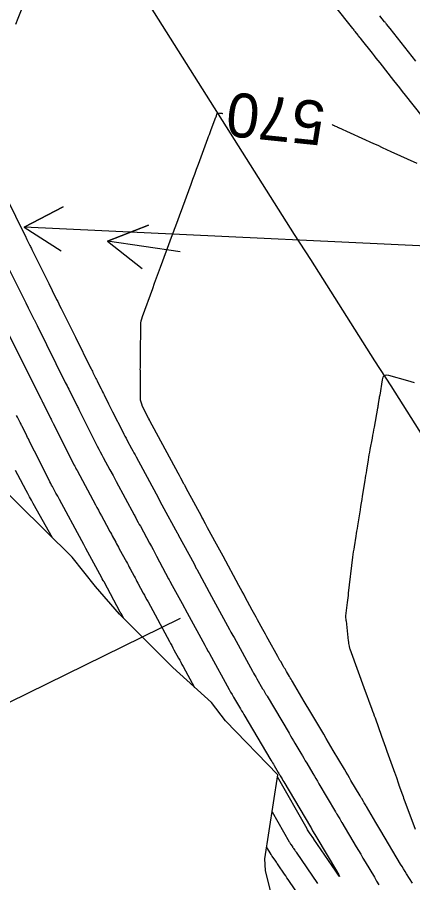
# Model space of a CAD drawing. Extents: x 954385 to 988206, y 1868364 to 1924553.
# Drawn here: x 957284.9 to 957338.9, y 1920532.9 to 1920650.9 of the extents above; entities that cross this region are included whole.
import ezdxf

# ---------------------------------------------------------------- set-up
doc = ezdxf.new("R2010")
doc.units = 0
for name, color, linetype in [('24', 7, 'Continuous'), ('26', 7, 'Continuous'), ('5', 7, 'Continuous'), ('6', 7, 'Continuous'), ('7', 7, 'Continuous'), ('Default', 7, 'Continuous')]:
    doc.layers.add(name, color=color, linetype=linetype)

msp = doc.modelspace()

# ---------------------------------------------------------------- linework, layer by layer
at = {"layer": '24'}
msp.add_lwpolyline([(957321.31, 1920524.25), (957318.76, 1920534.56), (957318.67, 1920536.13), (957320.46, 1920547.59), (957313.34, 1920554.95), (957311.39, 1920557.45), (957306.13, 1920562.25), (957298.87, 1920569.52), (957295.57, 1920573.3), (957292.4, 1920577.31), (957285.05, 1920584.53), (957280.11, 1920589.4)], dxfattribs=at)
at = {"layer": '26'}
for points in [[(957357.13, 1920618.93), (957285.84, 1920622.32), (957291.17, 1920625.07), (957285.84, 1920622.32), (957290.89, 1920619.08)], [(957307.13, 1920618.93), (957297.23, 1920620.38), (957302.81, 1920622.59), (957297.23, 1920620.38), (957301.94, 1920616.66)], [(957307.13, 1920568.93), (957203.18, 1920517.93), (957206.53, 1920522.91), (957203.18, 1920517.93), (957209.17, 1920517.53)]]:
    msp.add_lwpolyline(points, dxfattribs=at)
at = {"layer": '6'}
for points in [[(957338.83, 1920532.81), (957338.02, 1920534.11), (957337.82, 1920534.44), (957337.62, 1920534.77), (957337.42, 1920535.1), (957337.22, 1920535.43), (957334.53, 1920539.96), (957333.84, 1920541.1), (957332.55, 1920543.28), (957332.52, 1920543.34), (957332.48, 1920543.39), (957332.45, 1920543.45), (957332.42, 1920543.5), (957332.25, 1920543.78), (957332.19, 1920543.9), (957332.15, 1920543.95), (957331.9, 1920544.39), (957331.84, 1920544.48), (957331.79, 1920544.57), (957331.74, 1920544.66), (957331.68, 1920544.76), (957330.44, 1920546.85), (957330.22, 1920547.22), (957330, 1920547.6), (957329.77, 1920547.98), (957329.55, 1920548.36), (957328.03, 1920550.92), (957327.7, 1920551.48), (957327.37, 1920552.03), (957327.04, 1920552.58), (957326.72, 1920553.14), (957324.96, 1920556.11), (957324.06, 1920557.62), (957322.46, 1920560.32), (957322.36, 1920560.49), (957322.26, 1920560.66), (957322.15, 1920560.84), (957322.05, 1920561.01), (957321.64, 1920561.71), (957321.54, 1920561.88), (957321.44, 1920562.05), (957321.34, 1920562.21), (957321.25, 1920562.38), (957320.85, 1920563.05), (957320.75, 1920563.22), (957320.66, 1920563.39), (957320.56, 1920563.56), (957320.47, 1920563.73), (957319.16, 1920566.1), (957318.97, 1920566.43), (957318.79, 1920566.77), (957318.61, 1920567.1), (957318.43, 1920567.43), (957317.69, 1920568.75), (957317.51, 1920569.09), (957317.33, 1920569.42), (957317.15, 1920569.75), (957316.97, 1920570.08), (957316.02, 1920571.83), (957315.8, 1920572.23), (957315.58, 1920572.63), (957315.37, 1920573.03), (957315.15, 1920573.43), (957312.98, 1920577.42), (957312.76, 1920577.84), (957312.53, 1920578.25), (957312.31, 1920578.67), (957312.08, 1920579.08), (957310.88, 1920581.31), (957310.74, 1920581.57), (957310.6, 1920581.83), (957310.32, 1920582.36), (957310.25, 1920582.49), (957310.18, 1920582.62), (957310.1, 1920582.75), (957310.03, 1920582.88), (957308.23, 1920586.21), (957307.86, 1920586.9), (957307.8, 1920587), (957307.75, 1920587.1), (957307.69, 1920587.19), (957307.64, 1920587.29), (957307.22, 1920588.08), (957307.04, 1920588.41), (957306.86, 1920588.73), (957303, 1920595.88), (957302.98, 1920595.91), (957302.97, 1920595.94), (957302.95, 1920595.97), (957302.94, 1920596), (957302.81, 1920596.25), (957302, 1920597.85), (957301.88, 1920598.14), (957301.79, 1920598.43), (957301.74, 1920598.72), (957301.72, 1920599.03), (957301.71, 1920600.69), (957301.71, 1920600.93), (957301.71, 1920601.17), (957301.7, 1920601.42), (957301.7, 1920601.66), (957301.7, 1920602.69), (957301.69, 1920602.91), (957301.7, 1920603.12), (957301.7, 1920603.33), (957301.7, 1920603.54), (957301.72, 1920604.8), (957301.72, 1920605.22), (957301.74, 1920606.48), (957301.74, 1920606.76), (957301.75, 1920607.04), (957301.75, 1920607.32), (957301.75, 1920607.6), (957301.77, 1920608.9), (957301.78, 1920609.2), (957301.83, 1920609.51), (957301.89, 1920609.8), (957301.99, 1920610.1), (957303.38, 1920613.92), (957303.65, 1920614.65), (957303.92, 1920615.39), (957304.19, 1920616.12), (957304.46, 1920616.86), (957306.08, 1920621.28), (957306.17, 1920621.52), (957306.26, 1920621.77), (957306.35, 1920622.01), (957306.44, 1920622.25), (957306.8, 1920623.23), (957306.89, 1920623.47), (957306.98, 1920623.72), (957307.07, 1920623.96), (957307.16, 1920624.2), (957308.62, 1920628.18), (957308.87, 1920628.86), (957309.12, 1920629.53), (957309.37, 1920630.21), (957309.62, 1920630.88), (957310.92, 1920634.39), (957311.02, 1920634.66), (957311.12, 1920634.93), (957311.22, 1920635.2), (957311.32, 1920635.47), (957311.91, 1920637.07), (957311.96, 1920637.22), (957311.98, 1920637.26), (957312.07, 1920637.49), (957312.09, 1920637.57), (957312.12, 1920637.65), (957312.18, 1920637.8), (957312.2, 1920637.84), (957312.22, 1920637.86), (957312.25, 1920637.87), (957312.29, 1920637.87), (957312.5, 1920637.86), (957312.58, 1920637.85), (957312.81, 1920637.83), (957312.9, 1920637.82), (957312.96, 1920637.81)], [(957327.88, 1920636.28), (957327.91, 1920636.26), (957327.99, 1920636.23), (957328.06, 1920636.2), (957328.13, 1920636.17), (957328.2, 1920636.13), (957328.48, 1920636.01), (957328.55, 1920635.98), (957328.62, 1920635.94), (957328.69, 1920635.91), (957328.76, 1920635.88), (957333.5, 1920633.73), (957334.09, 1920633.46), (957334.69, 1920633.18), (957335.29, 1920632.91), (957335.89, 1920632.64), (957339.42, 1920631.03)], [(957289.71, 1920579.95), (957287.08, 1920584.62), (957286.83, 1920585.06), (957286.58, 1920585.51), (957286.34, 1920585.96), (957286.1, 1920586.4), (957284.97, 1920588.5), (957284.65, 1920589.1)], [(957325.31, 1920528.3), (957322.05, 1920533.08), (957321.88, 1920533.33), (957321.71, 1920533.58), (957321.54, 1920533.83), (957321.37, 1920534.08), (957320.51, 1920535.33), (957320.42, 1920535.46), (957320.34, 1920535.58), (957320.26, 1920535.7), (957320.17, 1920535.82), (957319.7, 1920536.5), (957319.66, 1920536.56), (957319.59, 1920536.66), (957319.58, 1920536.68), (957319.56, 1920536.7), (957319.55, 1920536.73), (957319.54, 1920536.75), (957318.93, 1920537.81)]]:
    msp.add_lwpolyline(points, dxfattribs=at)
at = {"layer": '7'}
for points in [[(957287.37, 1920656.87), (957284.99, 1920650.74), (957284.67, 1920649.94)], [(957340.17, 1920637.42), (957337.88, 1920640.3), (957337.49, 1920640.81), (957337.09, 1920641.31), (957336.69, 1920641.82), (957336.29, 1920642.32), (957334.42, 1920644.69), (957334.15, 1920645.02), (957333.89, 1920645.35), (957333.63, 1920645.68), (957333.36, 1920646.02), (957331.86, 1920647.91), (957331.79, 1920648.01), (957331.71, 1920648.11), (957331.48, 1920648.39), (957331.41, 1920648.49), (957331.02, 1920648.99), (957330.94, 1920649.08), (957330.86, 1920649.18), (957330.78, 1920649.28), (957330.7, 1920649.38), (957325.88, 1920655.5)], [(957339.28, 1920644.95), (957335.78, 1920649.37), (957335.3, 1920649.98), (957335.23, 1920650.06), (957335.17, 1920650.15), (957335.1, 1920650.24), (957335.03, 1920650.32), (957334.4, 1920651.12)], [(957281.76, 1920629.62), (957286.07, 1920620.93), (957286.12, 1920620.83), (957286.22, 1920620.63), (957286.27, 1920620.53), (957286.63, 1920619.78), (957286.7, 1920619.65), (957286.77, 1920619.52), (957286.83, 1920619.38), (957286.9, 1920619.25), (957289.2, 1920614.6), (957289.66, 1920613.68), (957290.27, 1920612.45), (957290.43, 1920612.14), (957290.58, 1920611.83), (957290.73, 1920611.52), (957290.89, 1920611.21), (957292.84, 1920607.3), (957294.91, 1920603.12), (957294.99, 1920602.96), (957295.07, 1920602.8), (957295.15, 1920602.64), (957295.23, 1920602.48), (957295.55, 1920601.84), (957295.63, 1920601.68), (957295.71, 1920601.52), (957295.79, 1920601.36), (957295.87, 1920601.2), (957296.34, 1920600.26), (957296.44, 1920600.05), (957296.55, 1920599.84), (957296.65, 1920599.63), (957296.76, 1920599.42), (957297.37, 1920598.21), (957297.5, 1920597.94), (957297.64, 1920597.67), (957297.78, 1920597.4), (957297.91, 1920597.12), (957299.3, 1920594.37), (957299.45, 1920594.08), (957299.6, 1920593.79), (957299.75, 1920593.51), (957299.9, 1920593.22), (957300.51, 1920592.09), (957300.67, 1920591.81), (957300.82, 1920591.52), (957300.97, 1920591.24), (957301.13, 1920590.96), (957303.84, 1920585.94), (957304.11, 1920585.44), (957304.38, 1920584.95), (957304.64, 1920584.45), (957304.91, 1920583.95), (957306.49, 1920581.04), (957306.73, 1920580.6), (957306.77, 1920580.53), (957306.8, 1920580.47), (957306.84, 1920580.41), (957306.87, 1920580.34), (957309.02, 1920576.37), (957309.13, 1920576.15), (957309.16, 1920576.1), (957309.19, 1920576.04), (957309.38, 1920575.69), (957309.41, 1920575.64), (957311.42, 1920571.93), (957313.86, 1920567.45), (957313.91, 1920567.35), (957313.96, 1920567.26), (957314.01, 1920567.17), (957314.06, 1920567.07), (957314.32, 1920566.61), (957314.48, 1920566.33), (957317, 1920561.75), (957317.14, 1920561.49), (957317.29, 1920561.23), (957317.44, 1920560.97), (957317.59, 1920560.72), (957318.39, 1920559.34), (957318.49, 1920559.18), (957318.59, 1920559.01), (957318.79, 1920558.67), (957318.84, 1920558.59), (957318.89, 1920558.5), (957318.94, 1920558.42), (957318.99, 1920558.34), (957321.99, 1920553.27), (957322.19, 1920552.93), (957322.39, 1920552.59), (957322.6, 1920552.25), (957322.8, 1920551.91), (957323.6, 1920550.55), (957323.81, 1920550.21), (957324.01, 1920549.87), (957324.21, 1920549.53), (957324.41, 1920549.19), (957325.24, 1920547.78), (957325.45, 1920547.43), (957325.66, 1920547.09), (957325.86, 1920546.74), (957326.07, 1920546.39), (957328.33, 1920542.58), (957328.38, 1920542.49), (957328.43, 1920542.41), (957328.48, 1920542.32), (957328.52, 1920542.24), (957328.75, 1920541.86), (957328.82, 1920541.74), (957328.9, 1920541.61), (957329.04, 1920541.35), (957329.08, 1920541.29), (957329.12, 1920541.23), (957329.16, 1920541.16), (957329.19, 1920541.1), (957331.15, 1920537.81), (957331.46, 1920537.29), (957331.77, 1920536.77), (957332.08, 1920536.25), (957332.39, 1920535.73), (957333.63, 1920533.64), (957333.94, 1920533.12), (957334.26, 1920532.6)], [(957283.86, 1920616.43), (957286.07, 1920611.97), (957286.41, 1920611.29), (957287.12, 1920609.85), (957287.16, 1920609.77), (957287.2, 1920609.69), (957287.24, 1920609.61), (957287.28, 1920609.52), (957287.61, 1920608.88), (957291.46, 1920601.12), (957291.58, 1920600.89), (957291.7, 1920600.66), (957291.81, 1920600.42), (957291.93, 1920600.19), (957293.03, 1920597.97), (957293.1, 1920597.83), (957293.17, 1920597.7), (957293.24, 1920597.56), (957293.31, 1920597.43), (957294.27, 1920595.51), (957294.45, 1920595.15), (957294.64, 1920594.78), (957294.82, 1920594.42), (957295, 1920594.05), (957295.82, 1920592.43), (957296.02, 1920592.04), (957296.22, 1920591.65), (957296.43, 1920591.26), (957296.64, 1920590.87), (957297.53, 1920589.22), (957297.97, 1920588.41), (957298.4, 1920587.6), (957300.86, 1920583.05), (957300.93, 1920582.92), (957301, 1920582.79), (957301.07, 1920582.67), (957301.14, 1920582.54), (957301.42, 1920582.02), (957301.56, 1920581.76), (957301.7, 1920581.51), (957302.96, 1920579.18), (957303.2, 1920578.75), (957303.43, 1920578.32), (957303.66, 1920577.89), (957303.9, 1920577.45), (957305.56, 1920574.36), (957305.65, 1920574.19), (957305.74, 1920574.03), (957305.77, 1920573.99), (957305.79, 1920573.94), (957305.81, 1920573.9), (957305.83, 1920573.86), (957307.41, 1920570.96), (957308.1, 1920569.69), (957310.49, 1920565.3), (957310.54, 1920565.2), (957310.59, 1920565.1), (957310.64, 1920565.01), (957310.7, 1920564.91), (957310.96, 1920564.43), (957311.07, 1920564.24), (957311.12, 1920564.14), (957313.82, 1920559.25), (957313.87, 1920559.16), (957313.92, 1920559.07), (957313.97, 1920558.99), (957314.02, 1920558.9), (957314.23, 1920558.55), (957314.33, 1920558.37), (957314.43, 1920558.2), (957315.22, 1920556.85), (957315.37, 1920556.6), (957315.52, 1920556.34), (957315.67, 1920556.09), (957315.82, 1920555.84), (957319.5, 1920549.63), (957319.62, 1920549.44), (957319.73, 1920549.24), (957319.85, 1920549.05), (957319.96, 1920548.86), (957320.52, 1920547.92), (957320.58, 1920547.81), (957320.64, 1920547.71), (957320.71, 1920547.6), (957320.77, 1920547.49), (957321.03, 1920547.06), (957321.15, 1920546.85), (957321.28, 1920546.63), (957324.91, 1920540.5), (957324.99, 1920540.37), (957325.06, 1920540.24), (957325.14, 1920540.12), (957325.21, 1920539.99), (957325.73, 1920539.1), (957325.76, 1920539.06), (957325.78, 1920539.02), (957328.45, 1920534.53), (957328.78, 1920533.96), (957328.88, 1920533.76), (957328.74, 1920533.93), (957328.36, 1920534.47), (957325.39, 1920538.82), (957325.36, 1920538.86), (957324.8, 1920539.68), (957324.7, 1920539.82), (957324.61, 1920539.96), (957324.53, 1920540.1), (957324.44, 1920540.24), (957320.42, 1920547.33)], [(957283.85, 1920607.5), (957287.54, 1920600.08), (957287.7, 1920599.77), (957287.85, 1920599.45), (957288.16, 1920598.83), (957288.24, 1920598.67), (957288.32, 1920598.51), (957288.4, 1920598.36), (957288.48, 1920598.2), (957289.44, 1920596.26), (957289.51, 1920596.12), (957289.58, 1920595.98), (957289.72, 1920595.69), (957289.76, 1920595.62), (957289.79, 1920595.55), (957289.83, 1920595.48), (957289.87, 1920595.41), (957292.04, 1920591.09), (957292.64, 1920589.89), (957292.75, 1920589.69), (957292.85, 1920589.5), (957292.95, 1920589.3), (957293.06, 1920589.1), (957295.57, 1920584.45), (957295.78, 1920584.07), (957295.99, 1920583.69), (957296.19, 1920583.31), (957296.4, 1920582.93), (957297.39, 1920581.08), (957297.51, 1920580.86), (957297.63, 1920580.64), (957297.75, 1920580.42), (957297.87, 1920580.2), (957298.35, 1920579.33), (957298.46, 1920579.11), (957298.58, 1920578.89), (957298.7, 1920578.67), (957298.82, 1920578.45), (957299.8, 1920576.65), (957299.93, 1920576.41), (957300.06, 1920576.17), (957300.19, 1920575.92), (957300.32, 1920575.68), (957300.84, 1920574.71), (957300.98, 1920574.47), (957301.11, 1920574.22), (957301.24, 1920573.98), (957301.37, 1920573.74), (957302.09, 1920572.4), (957302.25, 1920572.09), (957302.42, 1920571.79), (957302.58, 1920571.49), (957302.75, 1920571.18), (957305.67, 1920565.81), (957305.82, 1920565.52), (957305.98, 1920565.24), (957306.14, 1920564.95), (957306.29, 1920564.66), (957306.91, 1920563.52), (957307.07, 1920563.23), (957307.22, 1920562.95), (957307.38, 1920562.66), (957307.54, 1920562.38), (957309.11, 1920559.53)], [(957339.09, 1920601.09), (957338.65, 1920601.21), (957338.21, 1920601.33), (957335.6, 1920602.07), (957335.25, 1920602.12), (957334.98, 1920602.04), (957334.8, 1920601.83), (957334.69, 1920601.49), (957334.36, 1920599.4), (957334.33, 1920599.25), (957334.31, 1920599.1), (957334.29, 1920598.95), (957334.26, 1920598.8), (957334.17, 1920598.2), (957334.14, 1920598.06), (957334.12, 1920597.91), (957334.09, 1920597.76), (957334.06, 1920597.61), (957333.59, 1920595.04), (957333.52, 1920594.67), (957333.45, 1920594.29), (957333.38, 1920593.91), (957333.32, 1920593.53), (957333.03, 1920591.97), (957332.97, 1920591.62), (957332.9, 1920591.27), (957332.84, 1920590.92), (957332.79, 1920590.56), (957332.56, 1920589.16), (957332.5, 1920588.81), (957332.44, 1920588.45), (957332.39, 1920588.1), (957332.33, 1920587.75), (957331.99, 1920585.62), (957331.91, 1920585.15), (957331.83, 1920584.68), (957331.76, 1920584.21), (957331.68, 1920583.73), (957331.33, 1920581.57), (957331.27, 1920581.22), (957331.21, 1920580.86), (957331.16, 1920580.5), (957331.1, 1920580.15), (957330.87, 1920578.72), (957330.81, 1920578.37), (957330.76, 1920578.01), (957330.71, 1920577.65), (957330.67, 1920577.29), (957330.08, 1920572.4), (957330.04, 1920572.08), (957330.01, 1920571.76), (957329.97, 1920571.44), (957329.93, 1920571.11), (957329.71, 1920569.31), (957329.71, 1920569.25), (957329.7, 1920569.19), (957329.71, 1920569.13), (957329.71, 1920569.07), (957329.74, 1920568.77), (957329.76, 1920568.65), (957329.77, 1920568.59), (957330.08, 1920565.88), (957330.09, 1920565.78), (957330.1, 1920565.69), (957330.11, 1920565.6), (957330.12, 1920565.51), (957330.18, 1920565.14), (957330.2, 1920565.05), (957330.22, 1920564.96), (957330.24, 1920564.88), (957330.27, 1920564.79), (957332.39, 1920559.02), (957332.62, 1920558.41), (957332.84, 1920557.8), (957333.29, 1920556.58), (957333.4, 1920556.28), (957333.51, 1920555.98), (957333.62, 1920555.67), (957333.73, 1920555.37), (957334.62, 1920552.9), (957334.8, 1920552.39), (957334.98, 1920551.87), (957335.17, 1920551.36), (957335.35, 1920550.85), (957336.43, 1920547.85), (957336.47, 1920547.73), (957336.51, 1920547.61), (957336.55, 1920547.49), (957336.59, 1920547.37), (957336.93, 1920546.37), (957336.94, 1920546.32), (957336.96, 1920546.27), (957336.98, 1920546.23), (957336.99, 1920546.18), (957337.46, 1920544.89), (957337.55, 1920544.66), (957337.63, 1920544.43), (957337.72, 1920544.2), (957337.8, 1920543.97), (957339.19, 1920540.19)], [(957299.39, 1920569), (957299.06, 1920569.61), (957299.04, 1920569.65), (957298.96, 1920569.79), (957296.74, 1920573.92), (957296.71, 1920573.97), (957296.69, 1920574.01), (957296.66, 1920574.06), (957296.64, 1920574.11), (957296.51, 1920574.34), (957296.43, 1920574.49), (957294.81, 1920577.47), (957294.54, 1920577.98), (957294.26, 1920578.49), (957293.98, 1920579.01), (957293.7, 1920579.52), (957290.65, 1920585.16), (957290.42, 1920585.6), (957290.18, 1920586.04), (957289.71, 1920586.91), (957289.59, 1920587.13), (957289.47, 1920587.35), (957289.36, 1920587.57), (957289.25, 1920587.79), (957287.26, 1920591.73), (957286.63, 1920592.99), (957286.52, 1920593.2), (957286.42, 1920593.41), (957286.31, 1920593.62), (957286.21, 1920593.83), (957285.55, 1920595.15), (957285.49, 1920595.27), (957285.43, 1920595.39), (957285.37, 1920595.52), (957285.31, 1920595.64), (957285.07, 1920596.12), (957284.94, 1920596.37), (957284.82, 1920596.61)], [(957319.68, 1920542.57), (957321.99, 1920538.49), (957322.04, 1920538.41), (957322.09, 1920538.33), (957322.14, 1920538.25), (957322.19, 1920538.17), (957322.44, 1920537.82), (957322.48, 1920537.76), (957322.52, 1920537.7), (957322.56, 1920537.63), (957322.61, 1920537.57), (957322.78, 1920537.32), (957322.82, 1920537.26), (957322.86, 1920537.2), (957322.91, 1920537.14), (957322.95, 1920537.08), (957325.88, 1920532.79)]]:
    msp.add_lwpolyline(points, dxfattribs=at)
at = {"layer": 'Default'}
msp.add_arc((966995.78, 1926764.93), 11459.16, 211.460692, 214.075074, dxfattribs=at)

# ---------------------------------------------------------------- texts
at = {"layer": '5'}
msp.add_text('570', height=6, rotation=174.128, dxfattribs=at).set_placement((957327.12, 1920639.37))

doc.saveas('drawing.dxf')
